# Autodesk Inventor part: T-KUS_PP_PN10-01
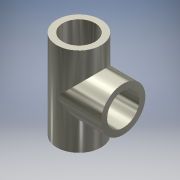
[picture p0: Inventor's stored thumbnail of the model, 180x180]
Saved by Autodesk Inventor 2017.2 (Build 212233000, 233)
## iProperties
Created: 2016-11
Part Number: T-KUS_PP_PN10-01
Material: Polypropylen
Document SubType Name: Modeling
Designer: CADstudio
Mass: 19.5818 g
Surface Area: 109.717 cm^2
Volume: 21.7818 cm^3
Density: 0.899 g/cm^3
Appearance: Hladká – popel
Vendor: KOWA
Categories: <MemberInstance><Categories><Category DisplayName="" InternalName="4347fa0f-2144-441d-94cd-e3e15c92b736" Mnemonic="TUBEANDPIPE"><CategoryParameter DisplayName="
Mass: 0,02
Author: CADstudio
Title: T-KUS PP PN10
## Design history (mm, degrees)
sketch "Náčrt1"
  geometry: C1 r 13.75 at (0, 0); C2 r 8.1 at (0, 0); 1 further point
  constraints: 2 centre point, 2 coincident
  dimensions: "EXTERNI" = 27.5 diameter of C1; "VNI" = 16.2 diameter of C2
extrude "Vysunutí1" new body sketch "Náčrt1" stored distance "d2" = 55 (= 2 x H_VYSUNUTI); taper "d3" = 0 deg
sketch "Náčrt2"
  geometry: L1 (13.75, -27.5)-(13.75, 27.5) reference; L2 (8.1, -27.5)-(8.1, 27.5) reference; 5 further points
  constraints: 2 coincident, 2 horizontal alignment, 2 midpoint, 4 other
extrude "Vysunutí2" join sketch "Náčrt2" distance "d4" = 27.5 (= H_VYSUNUTI); taper "d5" = 0 deg
feature "Odstranit plochu1"
feature "Odstranit plochu2"
sketch "Náčrt3"
  geometry: C1 r 8.1 at (0, 0) reference; C2 r 13.75 at (0, 0) reference; C3 r 10 at (0, 0)
  constraints: 1 centre point, 1 coincident
  dimensions: "VNE" = 20 diameter of C3
extrude "Vysunutí3" cut sketch "Náčrt3" distance "d7" = 14.5 (= H_VYSUNUTI - Z_VYSUNUTI); taper "d8" = 0 deg
sketch "Náčrt4"
  geometry: C1 r 8.1 at (0, 0) reference; C2 r 13.75 at (0, 0) reference; C3 r 10 at (0, 0)
  constraints: 1 centre point, 1 coincident
  dimensions: "d9" = 20 diameter of C3 (= VNE)
extrude "Vysunutí4" cut sketch "Náčrt4" distance "d10" = 14.5 (= H_VYSUNUTI - Z_VYSUNUTI); taper "d11" = 0 deg
sketch "Náčrt5"
  geometry: C1 r 8.1 at (0, 0) reference; C2 r 13.75 at (0, 0) reference; C3 r 10 at (0, 0)
  constraints: 1 centre point, 1 coincident
  dimensions: "d12" = 20 diameter of C3 (= VNE)
extrude "Vysunutí5" cut sketch "Náčrt5" distance "d13" = 14.5 (= H_VYSUNUTI - Z_VYSUNUTI); taper "d14" = 0 deg
node "Pracovní bod1"
node "Pracovní bod2"
node "Pracovní bod3"
node "Pracovní osa1"
node "Těleso1"
other parameters: "H_VYSUNUTI" = 27.5 [user parameter; used in 5 equation terms], "Z_VYSUNUTI" = 13 [user parameter; used in 3 equation terms]
